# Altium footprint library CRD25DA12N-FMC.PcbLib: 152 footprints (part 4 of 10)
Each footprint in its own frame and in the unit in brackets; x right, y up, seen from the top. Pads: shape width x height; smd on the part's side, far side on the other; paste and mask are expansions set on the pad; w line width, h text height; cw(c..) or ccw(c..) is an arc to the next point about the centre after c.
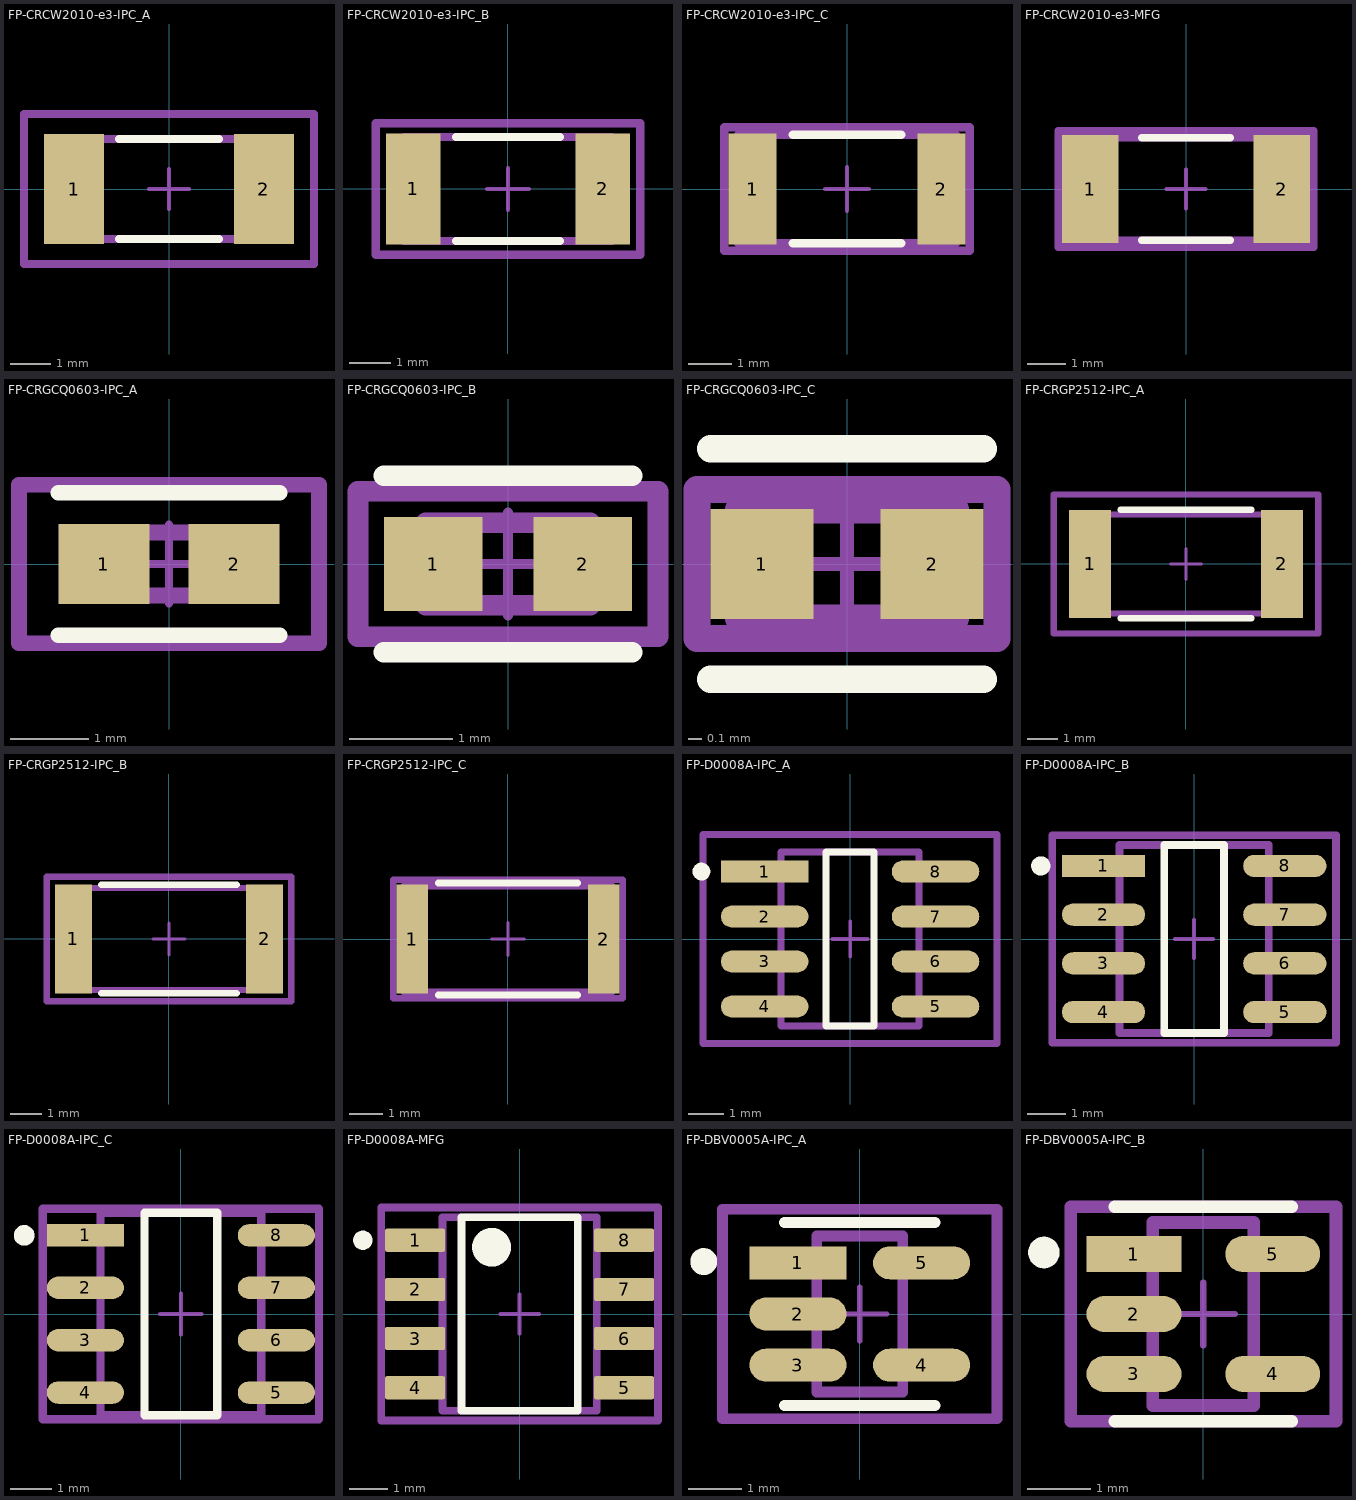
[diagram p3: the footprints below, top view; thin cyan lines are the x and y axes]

## FP-CRCW2010-e3-IPC_A [mm]
pads (2):
  rect 1.506x2.758 smd paste+0 mask+0: 1(-2.376,0) 2(2.376,0)
Top Overlay:
  lines w0.2: -1.248,-1.25 1.248,-1.25 ; -1.248,1.25 1.248,1.25
Top 3D Body:
  lines w0.2: -2.5,-1.25 -2.5,1.25 2.5,1.25 2.5,-1.25 -2.5,-1.25
Top Courtyard:
  lines w0.2: -3.629,-1.879 -3.629,1.879 3.629,1.879 3.629,-1.879 -3.629,-1.879
Top Assembly:
  lines w0.2: -3.629,-1.879 -3.629,1.879 3.629,1.879 3.629,-1.879 -3.629,-1.879
  text ".Designator" at 0,0.188 h1
Top Component Center:
  lines w0.1: -0.5,0 0.5,0 ; 0,-0.5 0,0.5
3D body "Res_Vishay_CRCW20106K04FKEF_eec.STEP": height 0.25, standoff 0, extent -3.629,-1.879 3.629,1.879

## FP-CRCW2010-e3-IPC_B [mm]
pads (2):
  rect 1.306x2.658 smd paste+0 mask+0: 1(-2.276,0) 2(2.276,0)
Top Overlay:
  lines w0.2: -1.248,-1.25 1.248,-1.25 ; -1.248,1.25 1.248,1.25
Top 3D Body:
  lines w0.2: -2.5,-1.25 2.5,-1.25 2.5,1.25 -2.5,1.25 -2.5,-1.25
Top Courtyard:
  lines w0.2: -3.179,-1.579 3.179,-1.579 3.179,1.579 -3.179,1.579 -3.179,-1.579
Top Assembly:
  lines w0.2: -3.179,-1.579 3.179,-1.579 3.179,1.579 -3.179,1.579 -3.179,-1.579
  text ".Designator" at 0,0.188 h1
Top Component Center:
  lines w0.1: -0.5,0 0.5,0 ; 0,-0.5 0,0.5
3D body "Res_Vishay_CRCW20106K04FKEF_eec.STEP": height 0.25, standoff 0, extent -3.179,-1.579 3.179,1.579

## FP-CRCW2010-e3-IPC_C [mm]
pads (2):
  rect 1.106x2.558 smd paste+0 mask+0: 1(-2.176,0) 2(2.176,0)
Top Overlay:
  lines w0.2: -1.248,-1.25 1.248,-1.25 ; -1.248,1.25 1.248,1.25
Top 3D Body:
  lines w0.2: -2.5,-1.25 2.5,-1.25 2.5,1.25 -2.5,1.25 -2.5,-1.25
Top Courtyard:
  lines w0.2: -2.829,-1.425 2.829,-1.425 2.829,1.425 -2.829,1.425 -2.829,-1.425
Top Assembly:
  lines w0.2: -2.829,-1.425 2.829,-1.425 2.829,1.425 -2.829,1.425 -2.829,-1.425
  text ".Designator" at 0,0.188 h1
Top Component Center:
  lines w0.1: -0.5,0 0.5,0 ; 0,-0.5 0,0.5
3D body "Res_Vishay_CRCW20106K04FKEF_eec.STEP": height 0.25, standoff 0, extent -2.829,-1.425 2.829,1.425

## FP-CRCW2010-e3-MFG [mm]
pads (2):
  rect 1.45x2.8 smd paste+0 mask+0: 1(-2.475,0) 2(2.475,0)
Top Overlay:
  lines w0.2: -1.145,-1.325 1.145,-1.325 ; -1.145,1.325 1.145,1.325
Top 3D Body:
  lines w0.2: -2.575,-1.325 2.575,-1.325 2.575,1.325 -2.575,1.325 -2.575,-1.325
Top Courtyard:
  lines w0.2: -3.3,-1.5 3.3,-1.5 3.3,1.5 -3.3,1.5 -3.3,-1.5
Top Assembly:
  lines w0.2: -3.3,-1.5 3.3,-1.5 3.3,1.5 -3.3,1.5 -3.3,-1.5
  text ".Designator" at 0,0.188 h1
Top Component Center:
  lines w0.1: -0.5,0 0.5,0 ; 0,-0.5 0,0.5
3D body "Res_Vishay_CRCW20106K04FKEF_eec.STEP": height 0.25, standoff 0, extent -3.3,-1.5 3.3,1.5

## FP-CRGCQ0603-IPC_A [mm]
pads (2):
  rect 1.158x1.012 smd paste+0 mask+0: 1(-0.827,0) 2(0.827,0)
Top Overlay:
  lines w0.2: -1.406,-0.906 1.406,-0.906 ; -1.406,0.906 1.406,0.906
Mechanical 5:
  lines w0.2: -1.906,-1.006 -1.906,1.006 1.906,1.006 1.906,-1.006 -1.906,-1.006
  text ".Designator" at 0,0.188 h1
Mechanical 13:
  lines w0.2: -0.8,-0.4 -0.8,0.4 0.8,0.4 0.8,-0.4 -0.8,-0.4
Mechanical 15:
  lines w0.2: -1.906,-1.006 -1.906,1.006 1.906,1.006 1.906,-1.006 -1.906,-1.006
Mechanical 16:
  lines w0.1: -0.5,0 0.5,0 ; 0,-0.5 0,0.5
3D body "Res_TE_Connectivity_CRGCQ0603F12R_eec.STEP": height 0.25, standoff 0, extent -1.906,-1.006 1.906,1.006

## FP-CRGCQ0603-IPC_B [mm]
pads (2):
  rect 0.958x0.912 smd paste+0 mask+0: 1(-0.727,0) 2(0.727,0)
Top Overlay:
  lines w0.2: -1.206,-0.856 1.206,-0.856 ; -1.206,0.856 1.206,0.856
Mechanical 5:
  lines w0.2: -1.456,-0.706 -1.456,0.706 1.456,0.706 1.456,-0.706 -1.456,-0.706
  text ".Designator" at 0,0.188 h1
Mechanical 13:
  lines w0.2: -0.8,-0.4 -0.8,0.4 0.8,0.4 0.8,-0.4 -0.8,-0.4
Mechanical 15:
  lines w0.2: -1.456,-0.706 -1.456,0.706 1.456,0.706 1.456,-0.706 -1.456,-0.706
Mechanical 16:
  lines w0.1: -0.5,0 0.5,0 ; 0,-0.5 0,0.5
3D body "Res_TE_Connectivity_CRGCQ0603F12R_eec.STEP": height 0.25, standoff 0, extent -1.456,-0.706 1.456,0.706

## FP-CRGCQ0603-IPC_C [mm]
pads (2):
  rect 0.758x0.812 smd paste+0 mask+0: 1(-0.627,0) 2(0.627,0)
Top Overlay:
  lines w0.2: -1.006,-0.85 1.006,-0.85 ; -1.006,0.85 1.006,0.85
Mechanical 5:
  lines w0.2: -1.106,-0.55 1.106,-0.55 1.106,0.55 -1.106,0.55 -1.106,-0.55
  text ".Designator" at 0,0.188 h1
Mechanical 13:
  lines w0.2: -0.8,-0.4 0.8,-0.4 0.8,0.4 -0.8,0.4 -0.8,-0.4
Mechanical 15:
  lines w0.2: -1.106,-0.55 1.106,-0.55 1.106,0.55 -1.106,0.55 -1.106,-0.55
Mechanical 16:
  lines w0.1: -0.5,0 0.5,0 ; 0,-0.5 0,0.5
3D body "Res_TE_Connectivity_CRGCQ0603F12R_eec.STEP": height 0.25, standoff 0, extent -1.106,-0.55 1.106,0.55

## FP-CRGP2512-IPC_A [mm]
pads (2):
  rect 1.358x3.506 smd paste+0 mask+0: 1(-3.102,0) 2(3.102,0)
Top Overlay:
  lines w0.2: -2.123,-1.753 2.123,-1.753 ; -2.123,1.753 2.123,1.753
Mechanical 5:
  lines w0.2: -4.281,-2.253 -4.281,2.253 4.281,2.253 4.281,-2.253 -4.281,-2.253
  text ".Designator" at 0,0.188 h1
Mechanical 13:
  lines w0.2: -3.175,-1.6 -3.175,1.6 3.175,1.6 3.175,-1.6 -3.175,-1.6
Mechanical 15:
  lines w0.2: -4.281,-2.253 -4.281,2.253 4.281,2.253 4.281,-2.253 -4.281,-2.253
Mechanical 16:
  lines w0.1: -0.5,0 0.5,0 ; 0,-0.5 0,0.5
3D body "Res_TE_CRGP2512F47R_eec.STEP": height 0.25, standoff 0, extent -4.281,-2.253 4.281,2.253

## FP-CRGP2512-IPC_B [mm]
pads (2):
  rect 1.158x3.406 smd paste+0 mask+0: 1(-3.002,0) 2(3.002,0)
Top Overlay:
  lines w0.2: -2.123,-1.703 2.123,-1.703 ; -2.123,1.703 2.123,1.703
Mechanical 5:
  lines w0.2: -3.831,-1.953 3.831,-1.953 3.831,1.953 -3.831,1.953 -3.831,-1.953
  text ".Designator" at 0,0.188 h1
Mechanical 13:
  lines w0.2: -3.175,-1.6 3.175,-1.6 3.175,1.6 -3.175,1.6 -3.175,-1.6
Mechanical 15:
  lines w0.2: -3.831,-1.953 3.831,-1.953 3.831,1.953 -3.831,1.953 -3.831,-1.953
Mechanical 16:
  lines w0.1: -0.5,0 0.5,0 ; 0,-0.5 0,0.5
3D body "Res_TE_CRGP2512F47R_eec.STEP": height 0.25, standoff 0, extent -3.831,-1.953 3.831,1.953

## FP-CRGP2512-IPC_C [mm]
pads (2):
  rect 0.958x3.306 smd paste+0 mask+0: 1(-2.902,0) 2(2.902,0)
Top Overlay:
  lines w0.2: -2.123,-1.7 2.123,-1.7 ; -2.123,1.7 2.123,1.7
Mechanical 5:
  lines w0.2: -3.481,-1.8 -3.481,1.8 3.481,1.8 3.481,-1.8 -3.481,-1.8
  text ".Designator" at 0,0.188 h1
Mechanical 13:
  lines w0.2: -3.175,-1.6 -3.175,1.6 3.175,1.6 3.175,-1.6 -3.175,-1.6
Mechanical 15:
  lines w0.2: -3.481,-1.8 -3.481,1.8 3.481,1.8 3.481,-1.8 -3.481,-1.8
Mechanical 16:
  lines w0.1: -0.5,0 0.5,0 ; 0,-0.5 0,0.5
3D body "Res_TE_CRGP2512F47R_eec.STEP": height 0.25, standoff 0, extent -3.481,-1.8 3.481,1.8

## FP-D0008A-IPC_A [mm]
pads (8):
  rect 2.469x0.622 smd paste+0 mask+0: 1(-2.414,1.905)
  rrect100% 2.469x0.622 smd paste+0 mask+0: 2(-2.414,0.635) 3(-2.414,-0.635) 4(-2.414,-1.905) 5(2.414,-1.905) 6(2.414,-0.635) 7(2.414,0.635) 8(2.414,1.905)
Top Overlay:
  circle w0.25: c-4.198,1.905 r0.125
  lines w0.2: -0.679,-2.452 0.679,-2.452 0.679,2.452 -0.679,2.452 -0.679,-2.452
Mechanical 5:
  lines w0.2: -4.148,-2.953 4.148,-2.953 4.148,2.953 -4.148,2.953 -4.148,-2.953
  text ".Designator" at 0,0.188 h1
Mechanical 13:
  lines w0.2: -1.947,-2.452 1.947,-2.452 1.947,2.452 -1.947,2.452 -1.947,-2.452
Mechanical 15:
  lines w0.2: -4.148,-2.953 4.148,-2.953 4.148,2.953 -4.148,2.953 -4.148,-2.953
Mechanical 16:
  lines w0.1: -0.5,0 0.5,0 ; 0,-0.5 0,0.5
3D body "IC_Texas_Instruments_ISO7220ADR_eec.STEP": height 0.25, standoff 0, extent -4.148,-2.953 4.148,2.953

## FP-D0008A-IPC_B [mm]
pads (8):
  rect 2.169x0.582 smd paste+0 mask+0: 1(-2.364,1.905)
  rrect100% 2.169x0.582 smd paste+0 mask+0: 2(-2.364,0.635) 3(-2.364,-0.635) 4(-2.364,-1.905) 5(2.364,-1.905) 6(2.364,-0.635) 7(2.364,0.635) 8(2.364,1.905)
Top Overlay:
  circle w0.25: c-3.998,1.905 r0.125
  lines w0.2: -0.779,-2.452 -0.779,2.452 0.779,2.452 0.779,-2.452 -0.779,-2.452
Mechanical 5:
  lines w0.2: -3.698,-2.702 -3.698,2.702 3.698,2.702 3.698,-2.702 -3.698,-2.702
  text ".Designator" at 0,0.188 h1
Mechanical 13:
  lines w0.2: -1.947,-2.452 -1.947,2.452 1.947,2.452 1.947,-2.452 -1.947,-2.452
Mechanical 15:
  lines w0.2: -3.698,-2.702 -3.698,2.702 3.698,2.702 3.698,-2.702 -3.698,-2.702
Mechanical 16:
  lines w0.1: -0.5,0 0.5,0 ; 0,-0.5 0,0.5
3D body "IC_Texas_Instruments_ISO7220ADR_eec.STEP": height 0.25, standoff 0, extent -3.698,-2.702 3.698,2.702

## FP-D0008A-IPC_C [mm]
pads (8):
  rect 1.869x0.542 smd paste+0 mask+0: 1(-2.314,1.905)
  rrect100% 1.869x0.542 smd paste+0 mask+0: 2(-2.314,0.635) 3(-2.314,-0.635) 4(-2.314,-1.905) 5(2.314,-1.905) 6(2.314,-0.635) 7(2.314,0.635) 8(2.314,1.905)
Top Overlay:
  circle w0.25: c-3.798,1.905 r0.125
  lines w0.2: -0.879,-2.452 -0.879,2.452 0.879,2.452 0.879,-2.452 -0.879,-2.452
Mechanical 5:
  lines w0.2: -3.348,-2.552 -3.348,2.552 3.348,2.552 3.348,-2.552 -3.348,-2.552
  text ".Designator" at 0,0.188 h1
Mechanical 13:
  lines w0.2: -1.947,-2.452 -1.947,2.452 1.947,2.452 1.947,-2.452 -1.947,-2.452
Mechanical 15:
  lines w0.2: -3.348,-2.552 -3.348,2.552 3.348,2.552 3.348,-2.552 -3.348,-2.552
Mechanical 16:
  lines w0.1: -0.5,0 0.5,0 ; 0,-0.5 0,0.5
3D body "IC_Texas_Instruments_ISO7220ADR_eec.STEP": height 0.25, standoff 0, extent -3.348,-2.552 3.348,2.552

## FP-D0008A-MFG [mm]
pads (8):
  rrect17% 1.55x0.6 smd paste+0 mask+0: 1(-2.7,1.905) 2(-2.7,0.635) 3(-2.7,-0.635) 4(-2.7,-1.905) 5(2.7,-1.905) 6(2.7,-0.635) 7(2.7,0.635) 8(2.7,1.905)
Top Overlay:
  circle w0.5: c-0.725,1.725 r0.25
  circle w0.25: c-4.05,1.905 r0.125
  lines w0.2: -1.5,-2.5 -1.5,2.5 1.5,2.5 1.5,-2.5 -1.5,-2.5
Mechanical 5:
  lines w0.2: -3.575,-2.75 -3.575,2.75 3.575,2.75 3.575,-2.75 -3.575,-2.75
  text ".Designator" at 0,0.188 h1
Mechanical 13:
  lines w0.2: -1.99,-2.5 -1.99,2.5 1.99,2.5 1.99,-2.5 -1.99,-2.5
Mechanical 15:
  lines w0.2: -3.575,-2.75 -3.575,2.75 3.575,2.75 3.575,-2.75 -3.575,-2.75
Mechanical 16:
  lines w0.1: -0.5,0 0.5,0 ; 0,-0.5 0,0.5
3D body "IC_Texas_Instruments_ISO7220ADR_eec.STEP": height 0.25, standoff 0, extent -3.575,-2.75 3.575,2.75

## FP-DBV0005A-IPC_A [mm]
pads (5):
  rect 1.805x0.612 smd paste+0 mask+0: 1(-1.15,0.95)
  rrect100% 1.805x0.612 smd paste+0 mask+0: 2(-1.15,0) 3(-1.15,-0.95) 4(1.15,-0.95) 5(1.15,0.95)
Top Overlay:
  circle w0.25: c-2.903,0.975 r0.125
  lines w0.2: -1.4,-1.7 1.4,-1.7 ; -1.4,1.7 1.4,1.7
Mechanical 5:
  lines w0.2: -2.553,-1.95 -2.553,1.95 2.553,1.95 2.553,-1.95 -2.553,-1.95
  text ".Designator" at 0,0 h1
Mechanical 13:
  lines w0.2: -0.8,-1.45 -0.8,1.45 0.8,1.45 0.8,-1.45 -0.8,-1.45
Mechanical 15:
  lines w0.2: -2.553,-1.95 -2.553,1.95 2.553,1.95 2.553,-1.95 -2.553,-1.95
Mechanical 16:
  lines w0.1: -0.5,0 0.5,0 ; 0,-0.5 0,0.5
3D body "IC_Texas_Instruments_SN74AHC1G00DBVR_eec.STEP": height 0.25, standoff 0, extent -2.553,-1.95 2.553,1.95

## FP-DBV0005A-IPC_B [mm]
pads (5):
  rect 1.505x0.572 smd paste+0 mask+0: 1(-1.1,0.95)
  rrect100% 1.505x0.572 smd paste+0 mask+0: 2(-1.1,0) 3(-1.1,-0.95) 4(1.1,-0.95) 5(1.1,0.95)
Top Overlay:
  circle w0.25: c-2.528,0.975 r0.125
  lines w0.2: -1.4,-1.7 1.4,-1.7 ; -1.4,1.7 1.4,1.7
Mechanical 5:
  lines w0.2: -2.103,-1.7 2.103,-1.7 2.103,1.7 -2.103,1.7 -2.103,-1.7
  text ".Designator" at 0,0 h1
Mechanical 13:
  lines w0.2: -0.8,-1.45 0.8,-1.45 0.8,1.45 -0.8,1.45 -0.8,-1.45
Mechanical 15:
  lines w0.2: -2.103,-1.7 2.103,-1.7 2.103,1.7 -2.103,1.7 -2.103,-1.7
Mechanical 16:
  lines w0.1: -0.5,0 0.5,0 ; 0,-0.5 0,0.5
3D body "IC_Texas_Instruments_SN74AHC1G00DBVR_eec.STEP": height 0.25, standoff 0, extent -2.103,-1.7 2.103,1.7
